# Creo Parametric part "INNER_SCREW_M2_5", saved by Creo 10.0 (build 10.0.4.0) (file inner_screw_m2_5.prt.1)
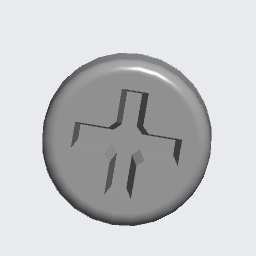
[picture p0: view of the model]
Units: millimeter Kilogram Sec (mmKs); MM, KILOGRAM, SECS

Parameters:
  PLACEMENT = "EXTERNAL"

Other parameters: MINOR_DIAMETER, PITCH

Created from: XX_SOLID_PART_MMKS_NEW_ABS.PRT

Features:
  1. datum plane "RIGHT"
  2. datum plane "TOP"
  3. datum plane "FRONT"
  4. coordinate system
  5. revolve "Revolve 1"
  6. feature "Cosmetic Thread 1"
  7. chamfer "Chamfer 1"
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
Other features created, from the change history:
  extruded cut "Extrude 1"
  chamfer "Chamfer 2"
